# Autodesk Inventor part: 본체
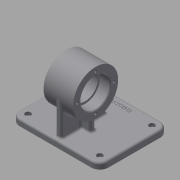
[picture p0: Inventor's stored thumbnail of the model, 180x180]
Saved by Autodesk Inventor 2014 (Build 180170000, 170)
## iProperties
Created: 2019-09
Part Number: 본체
Material: Generic
Document SubType Name: Modeling
Designer: kh
Density: 1 g/cm^3
Appearance: Default
Author: kh
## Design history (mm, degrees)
sketch "Sketch1"
  geometry: L1 (-63, -49)-(63, -49); L2 (63, -49)-(63, 49); L3 (63, 49)-(-63, 49); L4 (-63, 49)-(-63, -49); L5 (-63, -49)-(63, 49); L6 (63, -49)-(-63, 49); 1 further point
  constraints: 12 end point, 2 midpoint, 2 parallel, 1 horizontal, 1 perpendicular
  dimensions: "d0" = 126 distance of L2.end L3.end; "d1" = 98 distance of L1.end L2.end
extrude "Extrusion1" new body sketch "Sketch1" distance "d2" = 9; taper "d3" = 0 deg
workplane "Work Plane1"
sketch "Sketch2"
  geometry: L1 (126, 9)-(0, 9) reference; L2 (126, 0)-(0, 0) reference; L3 (63, 0)-(63, 59); L4 (63, 59)-(42, 59); L5 (42, 59)-(42, 91); L6 (42, 91)-(84, 91); L7 (84, 91)-(84, 59); L8 (84, 59)-(63, 59); L9 (42, 80)-(56.7, 80); L10 (57, 79.7)-(57, 77); L11 (57, 77)-(69, 77); L12 (69, 77)-(69, 79.7); L13 (69.3, 80)-(84, 80); A1 r 0.3 centre (56.7, 79.7) between (57, 79.7) and (56.7, 80); A2 r 0.3 centre (69.3, 79.7) between (69.3, 80) and (69, 79.7); 2 further points
  constraints: 22 end point, 6 point on line, 5 parallel, 4 perpendicular, 4 point on circle, 4 tangent, 2 centre point, 2 collinear, 1 equal radius, 1 other
  dimensions: "d5" = 59 distance of L3.start L3.end; "d6" = 64 diameter of L6 L4; "d7" = 42 diameter of L9 L4; "d8" = 42 diameter of L13 L8; "d9" = 36 diameter of L11 L8; "d10" = 15 distance of L9.start point (57, 80); "d11" = 15 distance of point (69, 80) L13.end; "d12" = 42 distance of L5.end L6.end; "d13" = 0.3 radius of A1
revolve "Revolution1" sketch "Sketch2" stored, may be unused: angle "d14" = 90 deg
chamfer "Chamfer1" distance "d15" = 1; stored, may be unused: second distance "d16" = 2, angle "d17" = 45 deg
sketch "Sketch3"
  geometry: L1 (42, 27)-(84, 27) reference; L2 (126, 9)-(0, 9) reference; L3 (63, 0)-(63, 27); L4 (46, 27)-(46, 9); L5 (80, 27)-(80, 9); L6 (80, 9)-(46, 9)
  constraints: 8 end point, 4 point on line, 2 perpendicular, 1 collinear, 1 midpoint, 1 other
  dimensions: "d18" = 34 distance of L5.end L4.end
feature "Rib1" sketch "Sketch3" dims "d19" = 1, "d20" = 8, "d21" = 0, "d22" = 0, "d23" = 1, "d24" = 1
sketch "Sketch4"
  geometry: L1 (49, 0)-(49, 9) reference; L2 (-49, 0)-(49, 0) reference; L3 (-13, 0)-(-13, 25.508); L4 (-49, 9)-(49, 9) reference; L5 (19, 59)-(19, 9); L6 (-45, 59)-(-45, 9); A1 r 32 centre (-13, 59) between (19, 59) and (-45, 59) reference; 1 further point
  constraints: 6 end point, 3 perpendicular, 3 point on line, 2 point on circle, 2 tangent
  dimensions: "d25" = 62 distance between parallel lines of L3 L1
feature "Rib2" dims "d26" = 1, "d27" = 8, "d28" = 0, "d29" = 0, "d30" = 1, "d31" = 1
feature "Rib3" dims "d32" = 1, "d33" = 8, "d34" = 0, "d35" = 0, "d36" = 1, "d37" = 1
fillet "Fillet1" dims "d38" = 12
sketch "Sketch5"
  geometry: L1 (-4, 19)-(4, 19) reference; L2 (4, 19)-(4, -9) reference; L3 (4, -9)-(17, -9) reference; L4 (17, -9)-(17, -17) reference; L5 (17, -17)-(4, -17) reference; L6 (4, -17)-(4, -45) reference; L7 (4, -45)-(-4, -45) reference; L8 (-4, -45)-(-4, -17) reference; L9 (-4, -17)-(-17, -17) reference; L10 (-17, -17)-(-17, -9) reference; L11 (-17, -9)-(-4, -9) reference; L12 (-4, -9)-(-4, 19) reference; L13 (63, -37)-(63, 37) reference; L14 (51, 49)-(-51, 49) reference; L15 (-63, 37)-(-63, -37) reference; L16 (-51, -49)-(51, -49) reference; A1 r 12 centre (51, -37) between (51, -49) and (63, -37) reference; A2 r 12 centre (51, 37) between (63, 37) and (51, 49) reference; A3 r 12 centre (-51, 37) between (-51, 49) and (-63, 37) reference; A4 r 12 centre (-51, -37) between (-63, -37) and (-51, -49) reference; 5 further points
  constraints: 4 coincident
hole "Hole1" sketch "Sketch5" at (-51, 37), (51, 37), (51, -37), (-51, -37) diameter "d39" = 4.5; stored, may be unused: countersink angle "d43" = 90 deg, drill point angle "d45" = 118 deg; dims "d40" = 6, "d41" = 8, "d42" = 4.4, "d44" = 8
sketch "Sketch6"
  geometry: L1 (0, 0)-(26, 0); C1 r 32 at (0, 0) reference; 2 further points
  constraints: 2 end point, 1 coincident, 1 horizontal
  dimensions: "d46" = 26 distance of L1.start L1.end
hole "Hole2" sketch "Sketch6" at (26, 0) diameter "d47" = 3.459; stored, may be unused: countersink angle "d51" = 90 deg, drill point angle "d53" = 118 deg; dims "d48" = 8, "d49" = 8, "d50" = 4.4, "d52" = 10
pattern_circular "Circular Pattern1" dims angle "d55" = 360 deg
mirror "Mirror1"
sketch "Sketch7"
  geometry: L1 (51, 49)-(-51, 49) reference; L2 (-13.921, 40.97)-(13.921, 40.97); L3 (13.921, 40.97)-(13.921, 37.03); L4 (13.921, 37.03)-(-13.921, 37.03); L5 (-13.921, 37.03)-(-13.921, 40.97); L6 (-13.921, 37.03)-(13.921, 40.97); L7 (63, -37)-(63, 37) reference; 2 further points
  constraints: 2 end point, 1 midpoint, 2 other
  dimensions: "d57" = 10 distance from line of L1 point (0, 39); "d58" = 63 distance from line of L7 point (0, 39)
extrude "Extrusion2" join sketch "Sketch7" distance "d59" = 0.5; taper "d60" = 0 deg
fillet "Fillet2" dims "d61" = 3
fillet "Fillet3" dims "d62" = 3
body "Solid1"
node "Projected Loop1"
other parameters: "d4" = -36
